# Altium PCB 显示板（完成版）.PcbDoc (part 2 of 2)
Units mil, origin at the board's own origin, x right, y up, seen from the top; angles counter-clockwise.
Board outline 5885.4 x 1803.57 mil, 2 copper layers (TOP, BOOTOM); 110 components, 88 nets, 770 pads, 302 vias.
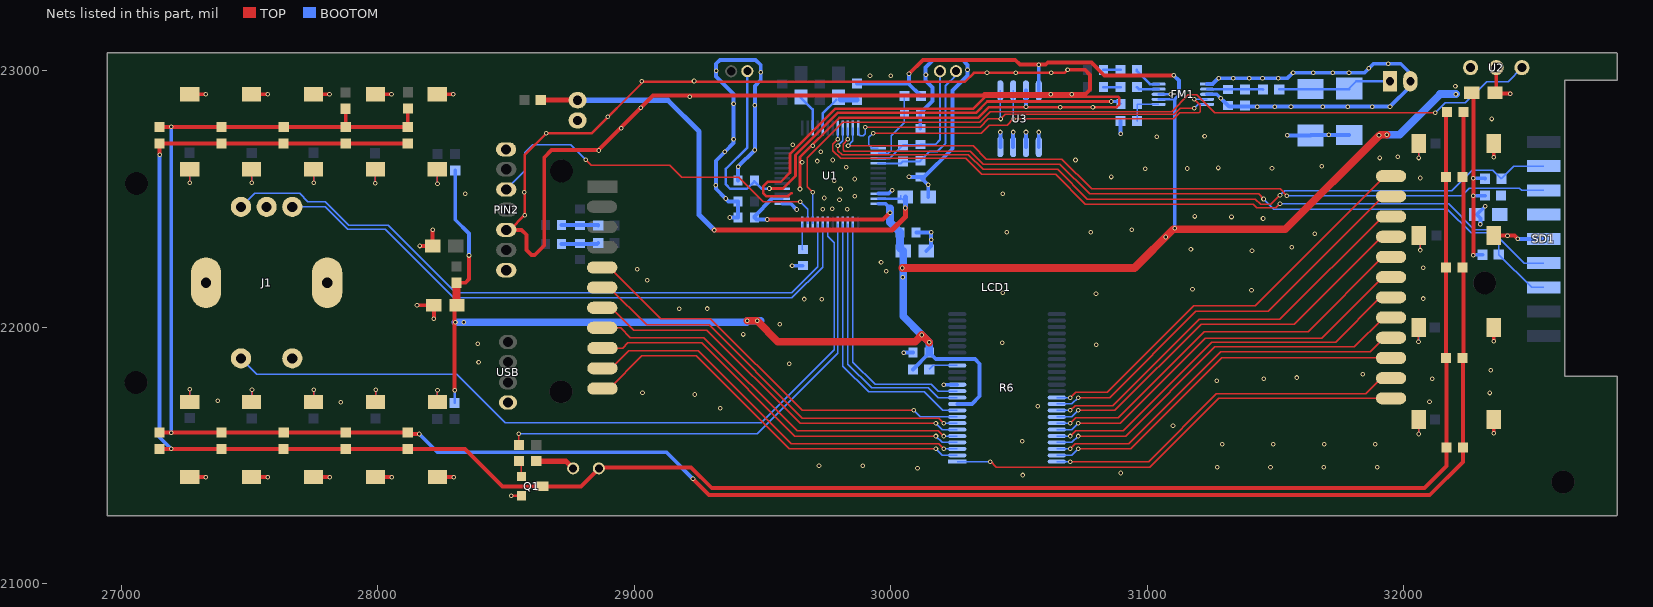
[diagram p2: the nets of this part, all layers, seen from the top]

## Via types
v1: diameter 18, hole 10, TOP to BOOTOM, tented both sides, 302 vias

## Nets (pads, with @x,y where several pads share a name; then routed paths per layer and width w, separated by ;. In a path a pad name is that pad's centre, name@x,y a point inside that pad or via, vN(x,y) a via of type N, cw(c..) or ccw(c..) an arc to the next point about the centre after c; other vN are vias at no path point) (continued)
GND: C1.1 C2.1 C3.2 C4.1 C5.1 C10.2 C11.1 C14.2 C15.1 C16.1 C17.1 C18.1 C19.2 C20.2 C26.1 C27.2 C28.2 D1.1 D2.2 FM1.1 FM1.3 FM1.8 J1.2 J1.4 J1.6 J1.7 PIN1.1 PIN2.1 PIN2.5 PIN2.7 Q1.2 R6.13 R36.1 R37.2 S1.2 S2.2 S3.2 S4.2 S5.2 S6.2 S7.2 S8.2 S9.2 S10.2 S11.2 S12.2 S13.2 S14.2 SD1.5 U1.1 U1.34 U2.2 U3.1 U3.2 U3.3 U3.4 U3.7 USB.1 | length 15564.7
  TOP w10: PIN2.5@28514,22379 28515,22379 v1(28573,22437) 28573,22672 v1(28657,22756) 28834,22756 29035,22957 30289,22957 30324,22992 30677,22992 v1(30689,23004) ; v1(28521,21343) Q1.2@28560,21343 ; 29613,22523 29612,22523 29600,22511 29514,22511 29503,22522 29503,22550 29520,22567 29571,22567 29607,22603 29607,22675 29784,22852 30322,22852 30369,22899 30886,22899 30891,22894 30891,22869 30880,22858 30382,22858 30340,22816 29799,22816 29646,22663 v1(29646,22539)
  TOP w15: S1.2@27266,22908.14 S1.2@27267,22908.14 v1(27329.14,22908.14) ; S2.2@27267,21415.86 v1(27330.14,21415.86) ; S3.2@27507.5,22908.14 S3.2@27508.25,22908.14 v1(27570.64,22908.14) ; S4.2@27508.5,21415.86 v1(27571.64,21415.86) ; S13.2@27749,22908.14 S13.2@27749.5,22908.14 v1(27812.14,22908.14) ; S7.2@27750,21415.86 v1(27813.14,21415.86) ; S14.2@27990.5,22908.14 S14.2@27990.75,22908.14 v1(28053.64,22908.14) ; S9.2@27991.5,21415.86 v1(28054.64,21415.86) ; v1(28153,22086) C28.2@28219,22086 v1(28219,22033) ; v1(28164,22317) C27.2@28214,22317 v1(28214,22380) ; S11.2@28232,22908.14 v1(28295.14,22908.14) ; S6.2@28233,21415.86 v1(28296.14,21415.86) ; PIN2.5@28501,22379.74 28560.78,22379.74 28580,22360.52 28580,22301 28599,22282 28612,22282 28649,22319 28649,22662 28678,22691 28861,22691 29073,22903 30359,22903 30365,22909 30760,22909 30777,22926 30777,22984 30757,23004 v1(30689,23004) ; v1(32350.14,21587.14) S8.2@32350.14,21640 ; v1(32350.14,21945.81) S12.2@32350.14,21998.67 ; S10.2@32350.14,22357.33 32431.15,22357.33 v1(32444,22344.49) ; v1(32350.14,22663.14) S5.2@32350.14,22716 ; U2.2@32360,23012 32360,22914 C14.2@32355,22914 32355,22911 v1(32415,22911)
  BOOTOM w10: FM1.8@31044.02,22908.32 v1(31091.32,22908.32)
  BOOTOM w15: v1(29372,22428) C3.2@29405.01,22428 C1.1@29405.01,22490 29368,22490 v1(29356,22502) 29318,22540 v1(29318,22554) 29318,22649 v1(29352.54,22683.54) 29387,22718 v1(29387,22733) v1(29387,22872) 29387,22910 29319,22978 v1(29319,23000) 29319,23027 29334,23042 29473,23042 29493,23022 v1(29493,22994) 29493,22964 29470,22941 v1(29470,22865) v1(29470,22691) v1(29405.01,22626.01) C2.1@29405.01,22572 ; U1.1@29576.99,22481.73 29610.27,22481.73 v1(29633,22459) ; v1(29615.01,22240.01) C5.1@29657,22240.01 ; U1.34@29951.01,22521.1 29992.1,22521.1 v1(30005,22534) ; v1(30050,21901) C20.2@30087.01,21901 ; v1(30071.01,22586.01) C18.1@30115,22586.01 ; C4.1@30098.99,22370 v1(30157,22370) v1(30157,22341) 30157,22316 C11.1@30138,22297 ; C17.1@30115,22774.99 30115,22834.01 C16.1@30115.99,22835 30163,22882.01 30163,22934 30135,22962 30135,23012 30166,23043 30279,23043 30299,23023 v1(30299,23004) 30299,22982 30240,22923 30240,22696 30130.01,22586.01 C18.1@30115,22586.01 ; C10.2@30146,22508 v1(30146,22555.01) C18.1@30115,22586.01 ; v1(30206,21776) R6.13@30259,21776 ; U3.4@30427,22703 v1(30427,22761) ; U3.3@30477,22703 v1(30477,22761) ; U3.2@30527,22703 v1(30527,22761) ; v1(30527,22859) U3.7@30527,22923 ; U3.1@30577,22703 v1(30577,22761) ; v1(30896,22754) R36.1@30896,22803.9 ; FM1.3@31233,22908.31 31270.69,22908.31 C26.1@31315,22864.01 31319.01,22860 v1(31428,22860) v1(31497,22860) v1(31560,22860) v1(31684,22860) v1(31781,22860) v1(31877,22860) v1(31946,22860) 32025,22939 PIN1.1@32025,22959 32025,22990 31988,23027 v1(31939,23027) 31881,23027 v1(31863.09,23009.09) 31846,22992 v1(31786,22992) v1(31723,22992) v1(31647,22992) v1(31568,22992) 31547,22971 v1(31510,22971) v1(31449,22971) v1(31397,22971) v1(31335,22971) v1(31278,22971) 31254.69,22947.69 FM1.1@31233,22947.69 ; v1(31545.9,22747.9) D2.2@31636,22747.9 31638,22749.9 v1(31707,22749.9) D1.1@31787,22749.9 ; v1(32298,22401) 32298,22425 C15.1@32284,22439 v1(32317,22472) ; v1(32444,22344.49) SD1.5@32545,22344.49
  other v1: 30514,21424 30896,21432 30104,21451 31272,21455 31480,21455 31688,21455 31896,21455 29720,21460 29890,21460 31292,21544 31490.67,21544 31689.33,21544 31888,21544 30513,21556 31100,21616 29335,21684 30573,21692 27856,21708 32100,21710 27376,21714 29236,21738 32334,21744 29032,21745 31270,21792 31454,21800 32110,21800 31583,21804 31840,21817 32338,21832 29604,21858 28393,21864 30801,21932 28390,21936 30435,21940 29425,21972 29567,22012 29175,22072 29284,22073 29731,22109 29662,22110 32075,22112 30800,22130 30436,22134 31406,22144 31176,22148 29050,22184 29982,22218 29012,22226 32075,22232 29962,22253 31408,22298 31170,22304 31563,22312 32404,22357.33 31652,22365 30452,22370 30780,22370 30939,22380 31451,22424 31328,22430 31185,22432 29734,22460 29830,22460 29772,22462 29800,22497 29740,22504 29860,22511 28341,22520 30436,22520 28571,22527 29804,22539 29780,22571 29860,22578 32064,22582 30860,22586 30992,22618 31156,22619 31486,22620 31276,22621 29826,22624 31680,22627 29654,22644 29713,22648 29774,22652 30720,22652 31906,22660 31976,22664 29727,22684 28861,22689 29696,22708 29618,22712 31036,22743 31223,22744 28950,22776 32342,22812 28896,22821 29026,22855 30661,22858 30788,22858 31285.78,22893.23 29217,22898 30623,22909 30706,22909 29029,22959 29233,22960 29919,22980 30000,22981 30137,22984 30375,22992 30487,22992 30625,22992
HTCS: R6.9 U1.40 | length 1072
  BOOTOM w5: U1.40@29813.21,22402.99 29813.21,21848.11 29913.32,21748 30130,21748 30202,21676 R6.9@30259,21676
HTDATA: R6.12 U1.38 | length 992
  BOOTOM w5: U1.38@29852.58,22402.99 29852.58,21864.42 29939,21778 30158,21778 30185,21751 R6.12@30259,21751
HTWR: R6.11 U1.39 | length 1026.8
  BOOTOM w5: U1.39@29832.9,22402.99 29832.9,21856.26 29925.16,21764 30146,21764 30184,21726 R6.11@30259,21726
I2C_SCK: FM1.4 U1.25 U3.6 | length 1633.2
  TOP w5: v1(29932,22757) 30353,22757 30384,22788 30454,22788 v1(30478,22812) 31103,22812 31127,22836 31201,22836 31206,22841 31206,22866 v1(31183.37,22888.63)
  BOOTOM w5: v1(29932,22757) 29915,22740 29915,22711 29927.73,22698.27 U1.25@29951.01,22698.27 ; 30477,22859 30477,22871 ; U3.6@30477,22923 30477,22871 ; v1(30478,22812) 30477,22813 30477,22871 ; v1(31183.37,22888.63) FM1.4@31233,22888.63
I2C_SDA: FM1.5 U1.24 U3.5 | length 1578.8
  TOP w5: v1(29901,22780) 30348,22780 30380,22812 v1(30428,22812) 30446,22830 31104,22830 31128,22854 v1(31183,22854)
  BOOTOM w5: U1.24@29872.27,22777.01 29872.27,22754.73 29880,22747 29893,22747 29901,22755 v1(29901,22780) ; 30427,22859 30427,22875 ; U3.5@30427,22923 30427,22875 ; v1(30428,22812) 30427,22813 30427,22875 ; v1(31183,22854) 31197.95,22868.95 FM1.5@31233,22868.95
IRDO: U1.46 U2.1 | length 3255.5
  TOP w5: v1(29696,22527) 29675,22548 29675,22661 29813,22799 30346,22799 30388,22841 31095,22841 31160,22906 31193,22906 31263,22836 v1(32122,22836)
  BOOTOM w5: U1.46@29695.1,22402.99 29695.1,22526.1 v1(29696,22527) ; v1(32122,22836) 32161,22875 32240,22875 32323,22958 32406,22958 U2.1@32460,23012
KEY: J1.5 U1.43 | length 3035.6
  BOOTOM w5: J1.5@27467,21878.72 27528.72,21817 28308,21817 28497,21628 29495,21628 29780,21913 29780,22329.16 29754.16,22355 U1.43@29754.16,22402.99
KEY_GND: D3.2 D4.2 D5.2 D6.2 D7.2 D8.2 D9.2 D10.2 D11.2 D12.2 D13.2 D14.2 D15.2 D16.2 D17.2 D19.2 Q1.3 | length 8739.3
  TOP w15: D8.2@27149.9,21526 v1(27195,21526) D10.2@27391.66,21526 D9.2@27633.42,21526 D5.2@27875.18,21526 D16.2@28116.95,21526 28340,21526 28486,21380 Q1.3@28640,21380 28792,21380 D19.2@28862,21450 28866,21454 29221,21454 29302,21373 32080,21373 32166.75,21459.75 D14.2@32166.75,21531.1 32166.75,21879.74 D7.2@32164.75,21879.74 D4.2@32164.75,22232.42 D3.2@32164.75,22585.1 32164.75,22839.1 D17.2@32168.75,22839.1 ; v1(27149.9,22673.1) D11.2@27149.9,22716.75 D6.2@27391.66,22716.75 D13.2@27633.42,22716.75 D12.2@27875.18,22716.75 D15.2@28116.95,22716.75
  BOOTOM w15: v1(27149.9,22673.1) 27149.9,21571.1 v1(27195,21526)
LCD_BL: R2.1 U1.41 | length 1921.4
  TOP w5: R2.1@28550.1,21541.25 v1(28550.1,21584.9)
  BOOTOM w5: v1(28550.1,21584.9) 29479.9,21584.9 29793.53,21898.53 U1.41@29793.53,22402.99
MCLR: C16.2 R1.2 U1.26 | length 288.3
  BOOTOM w5: U1.26@29951.01,22678.58 29990.58,22678.58 30001,22689 30001,22746 30053,22798 C16.2@30053,22835 30053,22900 R1.2@30054,22901
MUTE: PIN2.3 U1.47 | length 1495.6
  TOP w5: v1(28811,22653) 28832,22632 29138,22632 29185,22585 29407,22585 29503,22489 v1(29647,22489)
  BOOTOM w5: PIN2.3@28501,22537.22 28573,22609.22 28573,22680 28605,22712 28752,22712 v1(28811,22653) ; v1(29647,22489) 29675.42,22460.58 U1.47@29675.42,22402.99 29675.42,22448.58
NetC5_2: C5.2 U1.48 | length 100.5
  BOOTOM w5: U1.48@29655.73,22402.99 29655.73,22304.27 C5.2@29657,22303
NetC6_2: C6.2 C23.2 R9.1 | length 143.2
  BOOTOM w15: C6.2@28717,22398 28858.65,22398 R9.1@28859.75,22396.9
NetC7_2: C7.2 C24.1 R10.1 | length 144.4
  BOOTOM w15: C7.2@28717,22325 28855.86,22325 R10.1@28859.75,22328.9
NetC8_2: C8.2 R13.1 | length 67
  BOOTOM w10: C8.2@30828.99,23003.05 30829.04,23003 R13.1@30896,23003
NetC9_2: C9.2 R17.1 | length 67
  BOOTOM w10: C9.2@30828.99,22936.05 30829.04,22936 R17.1@30896,22936
NetC10_1: C10.1 C19.1 R3.2 U1.35 | length 2036.8
  TOP w5: C19.1@28778.31,22885.95 C19.1@28779.23,22885.04
  TOP w20: R3.2@28635.62,22885.95 C19.1@28778.31,22885.95 ; v1(29312,22379) 30005,22379 30057,22431 v1(30057,22465)
  BOOTOM w5: C10.1@30039,22501.42 C10.1@30039,22514 ; C10.1@30045,22497 C10.1@30056,22508 C10.1@30057,22507
  BOOTOM w10: U1.35@29951.01,22501.42 C10.1@30039,22501.42
  BOOTOM w20: C19.1@28779.23,22885.04 29130.96,22885.04 29253,22763 29253,22438 v1(29312,22379) ; v1(30057,22465) C10.1@30057,22507
NetC12_2: C12.2 U1.15 | length 139.2
  BOOTOM w5: C12.2@29650,22894 C12.2@29650,22897.5
  BOOTOM w10: C12.2@29650,22894 29695.1,22848.9 U1.15@29695.1,22777.01
NetC13_1: C13.1 R7.1 U1.17 | length 207.8
  BOOTOM w5: C13.1@29796,22896 C13.1@29805,22887
  BOOTOM w10: U1.17@29734.47,22777.01 29734.47,22833.34 C13.1@29788,22886.87
  BOOTOM w20: C13.1@29805,22887 R7.1@29868,22887
NetC17_2: C17.2 R4.2 U1.27 Y2.2 | length 522.4
  BOOTOM w8: U1.27@29951.01,22658.9 29996.22,22658.9 R4.2@30046.95,22709.62 30112.62,22709.62 C17.2@30115,22712 30173,22712 30191.87,22730.87 Y2.2@30191.87,22982.57
NetC18_2: C18.2 R4.1 U1.28 Y2.1 | length 577.4
  BOOTOM w8: U1.28@29951.01,22639.21 30039.89,22639.21 R4.1@30047.05,22646.38 30112.38,22646.38 C18.2@30115,22649 30152,22686 30182,22686 30214,22718 30214,22942.49 Y2.1@30254.47,22982.96
NetC25_1: C25.1 FM1.6 R36.2 | length 150.1
  BOOTOM w5: R36.2@30959.25,22804 30961.12,22805.87 C25.1@30961.12,22870 31042.97,22870 FM1.6@31044.02,22868.94
NetC26_2: C26.2 FM1.2 R37.1 R38.2 | length 218.2
  BOOTOM w10: FM1.2@31233,22928 31314,22928 C26.2@31315,22927 R37.1@31380,22927 31450.65,22927 R38.2@31450.75,22926.9
NetD1_2: D1.2 D2.1 PIN1.2 R38.1 | length 480.1
  BOOTOM w5: D1.2@31787,22931 D1.2@31815,22959
  BOOTOM w10: R38.1@31514,22927 D1.2@31787,22927 ; D1.2@31815,22959 PIN1.2@31946.26,22959 31946.26,22937.26 PIN1.2@31936,22927
NetD3_1: D3.1 D4.1 D5.1 D6.1 D7.1 D8.1 D9.1 D10.1 D11.1 D12.1 D13.1 D14.1 D15.1 D16.1 D17.1 R28.1 R29.2 | length 9259.2
  TOP w15: D8.1@27150,21589.25 v1(27195,21589.25) D10.1@27391.76,21589.25 D9.1@27633.53,21589.25 D5.1@27875.29,21589.25 D16.1@28117.05,21589.25 28122.3,21584 v1(28162,21584) ; D11.1@27150,22780 D6.1@27391.76,22780 D13.1@27633.53,22780 D12.1@27875.29,22780 ; R29.2@27875,22852 27875.29,22851.71 D12.1@27875.29,22780 ; R28.1@28118,22853 28117.05,22852.05 D15.1@28117.05,22780 D12.1@27875.29,22780 ; v1(29229,21409) 29292,21346 32101,21346 32230,21475 D14.1@32230,21531 D7.1@32230,21879.63 ; D7.1@32228,21879.63 D7.1@32230,21879.63 ; D4.1@32232,22232.32 D7.1@32232,21879.63 ; D17.1@32232,22839 D7.1@32232,21879.63 ; D7.1@32230,21879.63 D7.1@32232,21879.63
  BOOTOM w15: v1(27195,21589.25) v1(27195,22781) ; v1(28162,21584) 28233,21513 29125,21513 v1(29229,21409)
NetD19_1: D19.1 R14.2 | length 155.6
  TOP w20: R14.2@28618,21478 28734,21478 D19.1@28762,21450
NetFM1_9: FM1.9 R17.2 | length 88.1
  BOOTOM w10: R17.2@30959.25,22936.1 30967.35,22928 FM1.9@31044.02,22928
NetFM1_10: FM1.10 R13.2 | length 110.3
  BOOTOM w10: R13.2@30959.25,23003.1 30959.25,22998.75 31010.31,22947.69 FM1.10@31044.02,22947.69
NetQ1_1: Q1.1 R2.2 | length 64.1
  TOP w5: R2.2@28550,21478 28560,21468 Q1.1@28560,21418
NetR5_2: R5.2 R6.16 | length 115.2
  BOOTOM w5: R5.2@30150,21836 30165,21851 R6.16@30259,21851
NetR20_2: R20.2 S1.1 | length 104.9
  TOP w5: v1(27267,22564) S1.1@27267,22615.86
  BOOTOM w5: v1(27267,22564) R20.2@27267,22617
NetR21_2: R21.2 S2.1 | length 96.3
  TOP w5: S2.1@27268,21711.14 v1(27268,21758)
  BOOTOM w5: R21.2@27267,21709 27267,21757 v1(27268,21758)
NetR22_2: R22.2 S3.1 | length 104.9
  TOP w5: v1(27509,22563) S3.1@27509,22614.86
  BOOTOM w5: v1(27509,22563) R22.2@27509,22616
NetR23_2: R23.2 S4.1 | length 96.3
  TOP w5: S4.1@27510,21709.14 v1(27510,21756)
  BOOTOM w5: R23.2@27509,21707 27509,21755 v1(27510,21756)
NetR24_2: R24.2 S5.1 | length 114.1
  TOP w5: S5.1@32057.86,22716 32057.86,22660 v1(32058,22660)
  BOOTOM w5: v1(32058,22660) 32058,22716 R24.2@32060,22716
NetR25_2: R25.2 S7.1 | length 96.3
  TOP w5: S7.1@27751,21710.14 v1(27751,21757)
  BOOTOM w5: R25.2@27750,21708 27750,21756 v1(27751,21757)
NetR26_2: R26.2 S9.1 | length 96.3
  TOP w5: S9.1@27992.5,21710.28 v1(27992.5,21757.14)
  BOOTOM w5: R26.2@27991.5,21708.14 27991.5,21756.14 v1(27992.5,21757.14)
NetR27_2: R27.2 S13.1 | length 104.9
  TOP w5: v1(27750,22564) S13.1@27750,22615.86
  BOOTOM w5: v1(27750,22564) R27.2@27750,22617
NetR30_1: R30.1 S8.1 | length 114.1
  TOP w5: S8.1@32057.72,21640 32057.72,21584 v1(32057.86,21584)
  BOOTOM w5: v1(32057.86,21584) R30.1@32057.86,21640 R30.1@32059.86,21640
NetR31_1: R31.1 S12.1 | length 114.1
  TOP w5: S12.1@32056.86,21999 32056.86,21943 v1(32057,21943)
  BOOTOM w5: v1(32057,21943) R31.1@32057,21999 R31.1@32059,21999
NetR32_1: R32.1 S14.1 | length 104.9
  TOP w5: v1(27990,22562) S14.1@27990,22613.86
  BOOTOM w5: v1(27990,22562) R32.1@27990,22615
NetR33_1: R33.1 S6.1 | length 96.3
  TOP w5: S6.1@28233,21708.14 v1(28233,21755)
  BOOTOM w5: R33.1@28232,21706 28232,21754 v1(28233,21755)
NetR34_1: R34.1 S10.1 | length 114.1
  TOP w5: S10.1@32063.86,22357 32063.86,22301 v1(32064,22301)
  BOOTOM w5: v1(32064,22301) R34.1@32064,22357 R34.1@32066,22357
NetR35_1: R35.1 S11.1 | length 104.9
  TOP w5: v1(28233,22559) S11.1@28233,22610.86
  BOOTOM w5: v1(28233,22559) R35.1@28233,22612
OSCO: C2.2 C25.2 U1.4 Y1.1 | length 2283.9
  TOP w10: v1@29532,22541 29579,22541 29628.5,22590.5 29628.5,22671.5 29793,22836 30332,22836 30376,22880 v1@30859,22880
  BOOTOM w5: C25.2@30888.13,22880 C25.2@30898.13,22870
  BOOTOM w10: Y1.1@29440.6,22998.39 29440.6,22701.6 29357,22618 29357,22557 29374,22540 29439,22540 29468,22569 29496.21,22540.79 U1.4@29576.99,22540.79 ; v1(30860,22880) C25.2@30888.13,22880
  other v1: 29527,22541
SD_CLK: SD1.7 U1.23 | length 2885.5
  TOP w5: v1(29833.37,22707.02) 30320.98,22707.02 30373,22655 30667,22655 30783,22539 31518,22539 v1(31544,22513)
  BOOTOM w5: v1(29833.37,22707.02) 29852.58,22726.23 U1.23@29852.58,22777.01 ; v1(31544,22513) 32225,22513 32254,22542 32450,22542 32458.54,22533.46 SD1.7@32545,22533.46
SD_CMD: R12.2 SD1.3 U1.22 | length 3071.8
  TOP w5: v1(29832.9,22732.49) 29814,22713.59 29814,22692 29819,22687 30309.63,22687 30361,22635.63 30658.98,22635.63 30774.98,22519.63 31433.37,22519.63 v1(31453,22500)
  BOOTOM w5: v1(29832.9,22732.49) U1.22@29832.9,22777.01 ; v1(31453,22500) 31492,22461 32170,22461 32262,22369 32328,22369 32370,22327 R12.2@32370,22283 32497.49,22155.51 SD1.3@32545,22155.51
SD_DET: SD1.4 U1.20 | length 3065.4
  TOP w5: v1(29793.53,22732.49) 29774,22712.96 29774,22689 29804,22659 30291.63,22659 30355,22595.63 30642.41,22595.63 30758.41,22479.63 31412.37,22479.63 31427,22465 31500,22465 v1@31514.63,22479.63 ; v1@31517,22479.63 v1@31514.63,22479.63 ; v1(31517,22482) v1@31514.63,22479.63
  BOOTOM w5: v1(29793.53,22732.49) U1.20@29793.53,22777.01 ; v1(31517,22482) 32174,22482 32275,22381 32338,22381 32469,22250 SD1.4@32545,22250
SD_DO: R11.1 SD1.8 U1.21 | length 3042
  TOP w5: v1(29794,22707.02) 29794,22689 29810,22673 30302.63,22673 30360,22615.63 30650.69,22615.63 30766.69,22499.63 31421.37,22499.63 31442,22479 31482,22479 v1(31517,22514)
  BOOTOM w5: v1(29794,22707.02) 29813.21,22726.23 U1.21@29813.21,22777.01 ; v1(31517,22514) 31536,22533 31756,22533 ; 31737,22533 31756,22533 ; SD1.8@32545,22627.95 32428.95,22627.95 R11.1@32380,22579 32347,22612 32266,22612 32187,22533 31756,22533
SDVDD: C15.2 R8.2 SD1.6
SEG0: LCD1.5 R6.8 | length 1625
  TOP w5: LCD1.5@28875,22232.93 28904.07,22232.93 29103,22034 29297,22034 29655,21676 v1(30089,21676)
  BOOTOM w5: v1(30089,21676) 30114,21651 R6.8@30259,21651
SEG1: LCD1.6 R6.7 | length 1603.1
  TOP w5: LCD1.6@28875,22154.93 28902.07,22154.93 29048,22009 29291.71,22009 29654.71,21646 30186,21646 v1(30206,21626)
  BOOTOM w5: v1(30206,21626) R6.7@30259,21626
SEG2: LCD1.7 R6.6 | length 1612.7
  TOP w5: LCD1.7@28875,22075.93 28911.07,22075.93 28998,21989 29129,21989 ; 29097,21989 29129,21989 ; v1(30176,21626) 29646.42,21626 29283.42,21989 29129,21989
  BOOTOM w5: v1(30176,21626) 30201,21601 R6.6@30259,21601
SEG3: LCD1.8 R6.5 | length 1586.8
  TOP w5: LCD1.8@28875,21997.93 28947.07,21997.93 28985,21960 29125,21960 ; 29097,21960 29125,21960 ; v1(30206,21576) 30185,21597 29634.41,21597 29271.41,21960 29125,21960
  BOOTOM w5: v1(30206,21576) R6.5@30259,21576
SEG4: LCD1.9 R6.4 | length 1625
  TOP w5: LCD1.9@28876,21918.93 28954.93,21918.93 28975,21939 29170,21939 ; 29097,21939 29170,21939 ; v1(30176,21576) 29625.71,21576 29262.71,21939 29170,21939
  BOOTOM w5: v1(30176,21576) 30201,21551 R6.4@30259,21551
SEG5: LCD1.10 R6.3 | length 1639.4
  TOP w5: LCD1.10@28876,21839.93 28910.93,21839.93 28979,21908 29167,21908 ; 29097,21908 29167,21908 ; v1(30206,21526) 30187,21545 29612.87,21545 29249.87,21908 29167,21908
  BOOTOM w5: v1(30206,21526) R6.3@30259,21526
SEG6: LCD1.11 R6.2 | length 1665.8
  TOP w5: LCD1.11@28876,21760.93 28901.93,21760.93 29030,21889 29166,21889 ; 29097,21889 29166,21889 ; v1(30176,21526) 29605,21526 29242,21889 29166,21889
  BOOTOM w5: v1(30176,21526) 30201,21501 R6.2@30259,21501
SEG7: LCD1.12 R6.1 | length 1819.1
  TOP w5: v1(30388,21476) 30388,21479 30412,21455 31010,21455 31277.86,21722.86 LCD1.12@31950,21722.86
  BOOTOM w5: R6.1@30259,21476 30385,21476 30388,21479 v1(30388,21476)
SEG8: LCD1.13 R6.48 | length 1437.9
  TOP w5: v1(30700,21476) 31005,21476 31269,21740 31851,21740 31912.6,21801.6 LCD1.13@31950,21801.6
  BOOTOM w5: R6.48@30647,21476 v1(30700,21476)
SEG9: LCD1.14 R6.47 | length 1460.1
  TOP w5: v1(30730,21526) 30936,21526 31290.34,21880.34 LCD1.14@31950,21880.34
  BOOTOM w5: R6.47@30647,21501 30705,21501 v1(30730,21526)
SEG10: LCD1.15 R6.46 | length 1482.4
  TOP w5: v1(30700,21526) 30719,21545 30928.13,21545 31287.13,21904 31869,21904 31924.08,21959.08 LCD1.15@31950,21959.08
  BOOTOM w5: R6.46@30647,21526 v1(30700,21526)
SEG11: LCD1.16 R6.45 | length 1504.6
  TOP w5: v1(30730,21576) 30915.29,21576 31263.29,21924 31807,21924 31920.82,22037.82 LCD1.16@31950,22037.82
  BOOTOM w5: R6.45@30647,21551 30705,21551 v1(30730,21576)
SEG12: LCD1.17 R6.44 | length 1526.9
  TOP w5: v1(30700,21576) 30721,21597 30906.59,21597 31251.59,21942 31734,21942 31908.56,22116.56 LCD1.17@31950,22116.56
  BOOTOM w5: R6.44@30647,21576 v1(30700,21576)
SEG13: LCD1.18 R6.43 | length 1549.2
  TOP w5: v1(30730,21626) 30894.58,21626 31225.58,21957 31680,21957 31918.3,22195.3 LCD1.18@31950,22195.3
  BOOTOM w5: R6.43@30647,21601 30705,21601 v1(30730,21626)
SEG14: LCD1.19 R6.42 | length 1571.4
  TOP w5: v1(30700,21626) 30721,21647 30885.88,21647 31221.88,21983 31627,21983 31918.04,22274.04 LCD1.19@31950,22274.04
  BOOTOM w5: R6.42@30647,21626 v1(30700,21626)
SEG15: LCD1.20 R6.41 | length 1593.7
  TOP w5: v1(30730,21676) 30873.87,21676 31209.87,22012 31573,22012 31913.78,22352.78 LCD1.20@31950,22352.78
  BOOTOM w5: R6.41@30647,21651 30705,21651 v1(30730,21676)
SEG16: LCD1.21 R6.40 | length 1615.9
  TOP w5: v1(30700,21676) 30719,21695 30866,21695 31202,22031 31517,22031 31917.52,22431.52 LCD1.21@31950,22431.52
  BOOTOM w5: R6.40@30647,21676 v1(30700,21676)
SEG17: LCD1.22 R6.39 | length 1638.2
  TOP w5: v1(30730,21726) 30853.16,21726 31189.16,22062 31471,22062 31919.26,22510.26 LCD1.22@31950,22510.26
  BOOTOM w5: R6.39@30647,21701 30705,21701 v1(30730,21726)
SEG18: LCD1.23 R6.38 | length 1660.5
  TOP w5: v1(30700,21726) 30721,21747 30844.46,21747 31180.46,22083 31420,22083 31926,22589 LCD1.23@31950,22589
  BOOTOM w5: R6.38@30647,21726 v1(30700,21726)
VDD33: C3.1 C4.2 C11.2 C14.1 C20.1 C28.1 FM1.7 L1.2 R1.1 R5.1 R6.10 R6.17 R7.2 R8.1 R11.2 R12.1 R18.2 R19.2 U1.2 U1.36 U2.3 U3.8 | length 10278.4
  TOP w15: v1(28299.9,21754.1) 28299.9,22081.1 28306.9,22088.1 C28.1@28309,22086 ; L1.2@28306.9,22173.75 28341.75,22173.75 28355.75,22187.75 v1(28355.75,22280) ; v1(29518,22420) 29970,22420 v1(29997,22447) ; v1(30071,22988) 30125,23042 30485,23042 30503,23024 v1(30577,23024) 30604,23024 30612,23032 30782,23032 30832,22982 v1(31103,22982) ; C14.1@32265,22914 32271,22914 v1(32271,22581) v1(32271,22512.9) v1(32271,22281)
  TOP w30: C28.1@28306.9,22088.1 L1.2@28306.9,22173.75 ; v1(29441,22025) v1(29479,22025) 29560,21944 30095,21944 v1(30121,21970) v1(30150,21941) ; v1(30045,22231) 30950,22231 31101,22382 31538,22382 31903,22747 31905,22747 31909,22751 v1(31933,22751)
  BOOTOM w10: R18.2@28299.9,21705.25 v1(28299.9,21754.1) ; 29537.42,22501.42 U1.2@29576.99,22501.42 ; FM1.7@31044.02,22888.63 31106.63,22888.63 31113,22895
  BOOTOM w15: R19.2@28302.1,22611.75 28302.1,22418.9 28355.75,22365.25 v1(28355.75,22280) ; v1(29518,22420) 29476,22420 C3.1@29468,22428 29468,22432 29537.42,22501.42 ; R7.2@29867.9,22950.25 30068.1,22950.25 ; U1.36@29951.01,22481.73 29979.27,22481.73 29997,22464 ; v1(30071,22988) 30071,22953.14 30068.1,22950.25 ; R5.1@30086.75,21835.9 30150,21899.14 C20.1@30150,21901 30175,21876 R6.17@30259,21876 30328,21876 30346,21858 30346,21731 30316,21701 R6.10@30259,21701 ; R1.1@30130.9,22901.1 R1.1@30117.25,22901.1 30068.1,22950.25 ; U3.8@30577,22923 v1(30577,23024) ; v1(31072,22352) v1(31106.63,22386.63) 31106.63,22888.63 31123,22905 31123,22962 v1(31103,22982) ; v1(32271,22281) 32271,22282.9 R12.1@32306.75,22282.9 ; v1(32271,22512.9) R8.1@32315.75,22512.9 ; v1(32271,22581) 32316.75,22581 R11.2@32316.75,22578.9
  BOOTOM w30: v1(28303,22020) v1(28335,22020) 29438,22020 v1@29443,22025 ; v1(29441,22025) v1@29443,22025 ; 29492,22025 v1(29479,22025) v1@29443,22025 ; 29997,22464 v1(29997,22447) 29997,22409 C4.2@30036,22370 30036,22309 C11.2@30048,22297 30048,22043 v1(30121,21970) v1(30150,21941) C20.1@30150,21901 ; v1(31933,22751) 31983,22751 32141,22909 v1(32203,22909)
  other v1: 30047,22195 31903,22749 32201,22939
VOL1: J1.1 U1.45 | length 2639.7
  BOOTOM w5: J1.1@27467,22469.28 27519.73,22522 27696,22522 27728,22490 27796,22490 27888,22398 28041,22398 28305,22134 29613,22134 29714.79,22235.79 U1.45@29714.79,22402.99
VOL2: J1.3 U1.44 | length 2432.8
  BOOTOM w5: J1.3@27667,22469.28 27795.72,22469.28 27882.69,22382.31 28028.85,22382.31 28296.85,22114.31 29614.31,22114.31 29734.47,22234.47 U1.44@29734.47,22402.99
pads on no net: R6.14 R6.15 R6.18 R6.19 R6.20 R6.25 R6.26 R6.27 R6.28 R6.29 R6.30 R6.31 R6.32 R6.33 R6.34 R6.35 R6.36 R6.37 SD1.1 SD1.2 SD1.9 U1.5 U1.6 U1.9 U1.10 U1.11 U1.12 U1.18 U1.19 U1.29 U1.30 U1.31 U1.37 U1.42

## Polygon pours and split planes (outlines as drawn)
VDD33 on TOP "BOTTOM-No Net" (hatched 90Degree grid 4 track 5, remove dead copper, pour order 1000): 32287,22904 32287,23035 32253,23035 32187,23035 32187,22992 32187,22897 32261,22897 32287,22897 32287,22904
AGND on TOP "BOTTOM-No Net" (hatched 90Degree grid 4 track 5, remove dead copper, pour order 1001): 29503,22869 29538,22869 29538,22853 29538,22827 29508,22827 29497,22827 29497,22857 29497,22869 29503,22869
VDD33 on TOP "BOTTOM-No Net" (hatched 90Degree grid 4 track 5, remove dead copper, pour order 1002): 28296,22180 28359,22180 28359,22154 28359,21998 28308,21998 28292,21998 28292,22170 28292,22180 28296,22180
VDD33 on TOP "BOTTOM-No Net" (hatched 90Degree grid 4 track 5, remove dead copper, pour order 1003): 30100,21978 30134,21978 30156,21956 30162,21950 30162,21928 30085,21928 30085,21944 30085,21978 30100,21978
VDD33 on TOP "BOTTOM-No Net" (hatched 90Degree grid 4 track 5, remove dead copper, pour order 1004): 29433,22048 29505,22048 29505,22030 29505,22001 29448,22001 29424,22001 29424,22030 29424,22048 29433,22048
GND on TOP "BOTTOM-No Net" (hatched 90Degree grid 4 track 5, remove dead copper, pour order 1005): 26948.18,23066.93 32828.55,23066.93 32828.55,22981 32828.55,22964.87 32751,22964.87 32624.41,22964.87 32624.41,22910 32624.41,21807.05 32710,21807.05 32828.55,21807.05 32828.55,21735 32828.55,21268.39 32722,21268.39 26948.18,21268.39 26948.18,23066.93
SDVDD on BOOTOM "BOTTOM-No Net" (hatched 90Degree grid 4 track 5, remove dead copper, pour order 1006): 32361,22524 32361,22415 32581,22415 32581,22473 32444,22473 32444,22524
VDD33 on BOOTOM "BOTTOM-No Net" (hatched 90Degree grid 4 track 5, remove dead copper, pour order 1007): 32183,22957 32226,22957 32226,22934 32226,22895 32216,22895 32169,22895 32169,22916 32169,22957 32183,22957
VDD33 on BOOTOM "BOTTOM-No Net" (hatched 90Degree grid 4 track 5, remove dead copper, pour order 1008): 31948,22771 31948,22731 31885,22731 31885,22771
VDD33 on BOOTOM "BOTTOM-No Net" (hatched 90Degree grid 4 track 5, remove dead copper, pour order 1009): 29421,22047 29507,22047 29507,22030 29507,22001 29455,22001 29421,22001 29421,22047
VDD33 on BOOTOM "BOTTOM-No Net" (hatched 90Degree grid 4 track 5, remove dead copper, pour order 1010): 28301,22047 28358,22047 28358,22030 28358,21997 28322,21997 28287,21997 28287,22026 28287,22047 28301,22047
GND on BOOTOM "BOTTOM-No Net" (hatched 90Degree grid 4 track 5, remove dead copper, pour order 1011): 26948.18,23066.93 32828.55,23066.93 32828.55,22981 32828.55,22964.87 32751,22964.87 32624.41,22964.87 32624.41,22910 32624.41,21807.05 32710,21807.05 32828.55,21807.05 32828.55,21735 32828.55,21268.39 32722,21268.39 26948.18,21268.39 26948.18,23066.93

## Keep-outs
Keep-Out Layer:
  lines w5: 26948.18,21268.39 28917.3,21268.39 ; 26948.18,21268.39 28917.3,21268.39 ; 26948.18,21268.39 26948.18,21295.39 ; 26948.18,21295.39 26948.18,23066.93 ; 26948.18,21295.39 26948.18,23066.93 ; 26948.18,21295.39 26948.18,21295.39 ; 26948.18,23066.93 32828.55,23066.93 32828.55,22964.87 32828.27,22964.87 ; 28917.3,21268.39 32010.34,21268.39 ; 28917.3,21268.39 28917.3,21268.39 ; 32010.34,21268.39 32828.55,21268.39 ; 32010.34,21268.39 32828.55,21268.39 ; 32624.41,21807.05 32624.41,22964.67 32624.41,22964.87 32686.82,22964.87 ; 32624.41,21807.05 32687.41,21807.05 ; 32624.41,21807.05 32687.41,21807.05 ; 32686.82,22964.87 32828.27,22964.87 ; 32686.82,22964.87 32828.27,22964.87 ; 32687.41,21807.05 32828.55,21807.05 32828.55,21268.39

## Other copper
TOP:
  pour cut-out: 28804.44,22573 28943,22573 28943,21753 28806,21753 28806,22570 28804.44,22570
  pour cut-out: 31890.57,22616 32008,22616 32008,21711 31860,21711 31860,22529 31888,22557 31888,22613.47
  pour cut-out: 31841,22836 31841,22796 32122,22796 32122,22836
  pour cut-out: 28355.75,22187.75 28402,22187.75 28402,21988 28355.75,21988
  text "TOP" at 26996,23209 h60
BOOTOM:
  rectangle net SDVDD: 32454,22421 32526,22460
  rectangle net GND: 32452,22325 32529,22365
  pour cut-out: 28637,22432 28964,22432 28964,22279 28503,22279 28503,22405 28637,22405
  pour cut-out: 29941,22433 29941,22213 29675,22213 29675,22433
  pour cut-out: 29710,22994 29850,22994 29850,22887 29719,22887 29719,22992
  pour cut-out: 29533,22873 29609.53,22873 29609.53,22837 29533,22837
  pour cut-out: 31005,23030 31005,22870 30969,22870 30969,22825 30875,22825 30875,22903.87 30746,22903.87 30746,23030
  pour cut-out: 31543,22971 31564,22992 31566,22990 32017,22990 32017,22902 31852,22902 31852,22874 31203,22874 31203,22971
  pour cut-out: 31646,22539 32344,22539 32344,22498 32284,22498 32284,22434 32224,22434 32183,22475 31645,22475 31645,22533
  pour cut-out: 32660,22755 32660,21930.41 32467.54,21930.41 32467.54,22755
  text "BOTTOM" at 28042,23219 h60

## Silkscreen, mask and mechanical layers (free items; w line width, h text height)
Top Overlay:
  text "高端、高速PCB设计文件与你共分享 PCB联盟网 www.pcbbar.com  QQ群:374116257" at 26545,23654 h196.85
  text "TOPSILK" at 26982,23341 h60
Bottom Overlay:
  lines w5: 30033,22778 30086,22778 ; 28973,22846 29272,22846 29272,22980 28997,22980 28973,22980 28973,22846 ; 29523,22838 29913,22838 29913,23041 29549,23041 29523,23041 29523,22838
  text "BOTTOMSILK" at 28047,23345 h60
  text "A" at 29560,22998 h30
  text "A" at 28981,22932 h30
Mechanical 1:
  lines w2: 27312.81,22235.85 27362.02,22235.85 27362.02,22115.26 27312.81,22115.26 27312.81,22237.26 ; 27237.06,22702.72 27237.06,22714.53 27237.06,22820.83 27296.12,22820.83 27296.12,22702.72 27237.06,22702.72 ; 27237.8,21500.76 27237.8,21618.87 27296.85,21618.87 27296.85,21607.06 27296.85,21500.76 27237.8,21500.76 ; 27312.81,21920.89 27824.62,21920.89 27824.62,22432.7 27336.98,22432.7 27312.81,22432.7 27312.81,21920.89 ; 27478.37,22702.72 27478.37,22714.53 27478.37,22820.83 27537.42,22820.83 27537.42,22702.72 27478.37,22702.72 ; 27478.69,21500.76 27478.69,21618.87 27537.74,21618.87 27537.74,21607.06 27537.74,21500.76 27478.69,21500.76 ; 27719.68,22702.72 27719.68,22714.53 27719.68,22820.83 27778.73,22820.83 27778.73,22702.72 27719.68,22702.72 ; 27720.05,21500.76 27720.05,21618.87 27779.11,21618.87 27779.11,21607.06 27779.11,21500.76 27720.05,21500.76 ; 27775.41,22117.74 27824.62,22117.74 27824.62,22235.85 27775.41,22235.85 27775.41,22117.74 ; 27960.47,21500.76 27960.47,21618.87 28019.53,21618.87 28019.53,21607.06 28019.53,21500.76 27960.47,21500.76 ; 27960.84,22702.71 27960.84,22714.53 27960.84,22820.82 28019.9,22820.82 28019.9,22702.71 27960.84,22702.71 ; 28202.29,22702.72 28202.29,22714.53 28202.29,22820.83 28261.34,22820.83 28261.34,22702.72 28202.29,22702.72 ; 28203.42,21500.77 28203.42,21618.88 28262.47,21618.88 28262.47,21607.07 28262.47,21500.77 28203.42,21500.77 ; 28937.99,21369.26 31831.99,21369.26 31831.99,22946.26 28937.99,22946.26 28937.99,21369.26 ; 32146.13,21610.23 32146.13,21669.29 32157.94,21669.29 32264.24,21669.29 32264.24,21610.23 32146.13,21610.23 ; 32146.13,21969.23 32146.13,22028.29 32157.94,22028.29 32264.24,22028.29 32264.24,21969.23 32146.13,21969.23 ; 32146.13,22328.23 32146.13,22387.29 32157.94,22387.29 32264.24,22387.29 32264.24,22328.23 32146.13,22328.23 ; 32146.13,22687.23 32264.24,22687.23 32264.24,22746.29 32157.94,22746.29 32146.13,22746.29 32146.13,22687.23
  lines w5: 32828.55,21528.39 32828.55,21268.39 ; 26948.18,21268.39 26948.18,21279.39 26948.18,21268.39 ; 26948.18,21268.39 26948.18,21295.39 ; 26948.18,21268.39 28917.3,21268.39 26948.18,21268.39 ; 26948.18,21268.39 26948.18,21295.39 ; 26948.18,21295.39 26948.18,23066.93 ; 26948.18,21295.39 26948.18,23066.93 ; 26948.18,23066.93 27311.18,23066.93 26948.18,23066.93 ; 32624.41,21807.05 32624.41,22964.67 32624.41,21807.05 ; 32624.41,21807.05 32687.41,21807.05 ; 32624.41,21807.05 32687.41,21807.05 ; 32687.41,21807.05 32829.14,21807.05 32687.41,21807.05 ; 32828.55,21268.39 32010.34,21268.39 32828.55,21268.39 ; 32828.55,21268.39 32828.55,21344.39 32828.55,21268.39 ; 26961.21,23066.93 28915.33,23066.93 26961.21,23066.93 ; 28785.69,23066.93 29162.09,23066.93 28785.69,23066.93 ; 28912.19,21268.39 30066.59,21268.39 28912.19,21268.39 ; 29149.59,21268.39 31777.54,21268.39 29149.59,21268.39 ; 29263.89,23066.93 32828.55,23066.93 29263.89,23066.93 ; 31765.19,21268.39 32112.79,21268.39 31765.19,21268.39 ; 32686.82,22964.87 32828.27,22964.87 32686.82,22964.87 ; 32828.55,21295.59 32828.55,21807.24 32828.55,21295.59 ; 32828.55,22964.87 32828.55,23067.25 32828.55,22964.87
  lines w10: 26822.18,21328.39 26842.18,21268.39 ; 26822.18,23006.93 26842.18,23066.93 ; 26832.18,21268.39 26935.68,21268.39 ; 26832.18,23066.93 26948.71,23066.93 ; 26842.18,21940.72 26842.18,21268.39 ; 26842.18,22362.6 26842.18,23066.93 ; 26862.18,21328.39 26842.18,21268.39 ; 26862.18,23006.93 26842.18,23066.93 ; 26948.18,21123.39 26948.18,21282.89 ; 27008.18,21113.39 26948.18,21133.39 ; 27008.18,21153.39 26948.18,21133.39 ; 29636.44,21133.39 26948.18,21133.39 ; 30108.3,21133.39 32828.55,21133.39 ; 32768.55,21113.39 32828.55,21133.39 ; 32768.55,21153.39 32828.55,21133.39 ; 32828.55,21123.39 32828.55,21255.89
Mechanical 2:
  lines w2: 32458.1,21919.79 32458.1,22774.12 32635.27,22774.12 32635.27,21919.79 32458.1,21919.79
  lines w5: 32624.41,22964.87 32686.82,22964.87 ; 32828.55,21528.39 32828.55,21268.39 ; 26948.18,21268.39 28917.3,21268.39 26948.18,21268.39 ; 26948.18,21268.39 26948.18,21295.39 ; 26948.18,21268.39 26948.18,21279.39 26948.18,21268.39 ; 26948.18,21268.39 26948.18,21295.39 ; 26948.18,21295.39 26948.18,23066.93 ; 26948.18,21295.39 26948.18,23066.93 ; 26948.18,23066.93 27311.18,23066.93 26948.18,23066.93 ; 32624.41,21807.05 32687.41,21807.05 ; 32624.41,21807.05 32624.41,22964.67 32624.41,21807.05 ; 32624.41,21807.05 32687.41,21807.05 ; 32686.82,22964.87 32828.27,22964.87 32686.82,22964.87 ; 32687.41,21807.05 32829.14,21807.05 32687.41,21807.05 ; 32828.55,21268.39 32828.55,21344.39 32828.55,21268.39 ; 32828.55,21268.39 32010.34,21268.39 32828.55,21268.39 ; 26961.21,23066.93 28915.33,23066.93 26961.21,23066.93 ; 28785.69,23066.93 29162.09,23066.93 28785.69,23066.93 ; 28912.19,21268.39 30066.59,21268.39 28912.19,21268.39 ; 29149.59,21268.39 31777.54,21268.39 29149.59,21268.39 ; 29263.89,23066.93 32828.55,23066.93 29263.89,23066.93 ; 31765.19,21268.39 32112.79,21268.39 31765.19,21268.39 ; 32828.55,21295.59 32828.55,21807.24 32828.55,21295.59 ; 32828.55,22964.87 32828.55,23067.25 32828.55,22964.87
  text "S1" at 27285.98,22905.26 h60 r90
  text "S3" at 27525.98,22905.26 h60 r90
  text "S13" at 27762.98,22905.26 h60 r90
  text "S14" at 27998.98,22905.26 h60 r90
  text "S11" at 28253.98,22905.26 h60 r90
  text "S5" at 31957.99,22686.26 h60
  text "S10" at 31924.99,22336.26 h60
  text "LCD" at 30143.99,22024.26 h200
  text "S12" at 31933.99,21975.26 h60
  text "45.68mm" at 26878.17,21956.72 h60 r90
  text "S8" at 31959.99,21615.26 h60
  text "S2" at 27275.98,21401.84 h60 r90
  text "S7" at 27758.98,21401.6 h60 r90
  text "S9" at 27992.98,21401.37 h60 r90
  text "S6" at 28257.98,21401.14 h60 r90
  text "S4" at 27504.98,21400.26 h60 r90
  text "149.36mm" at 29652.44,21097.4 h60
